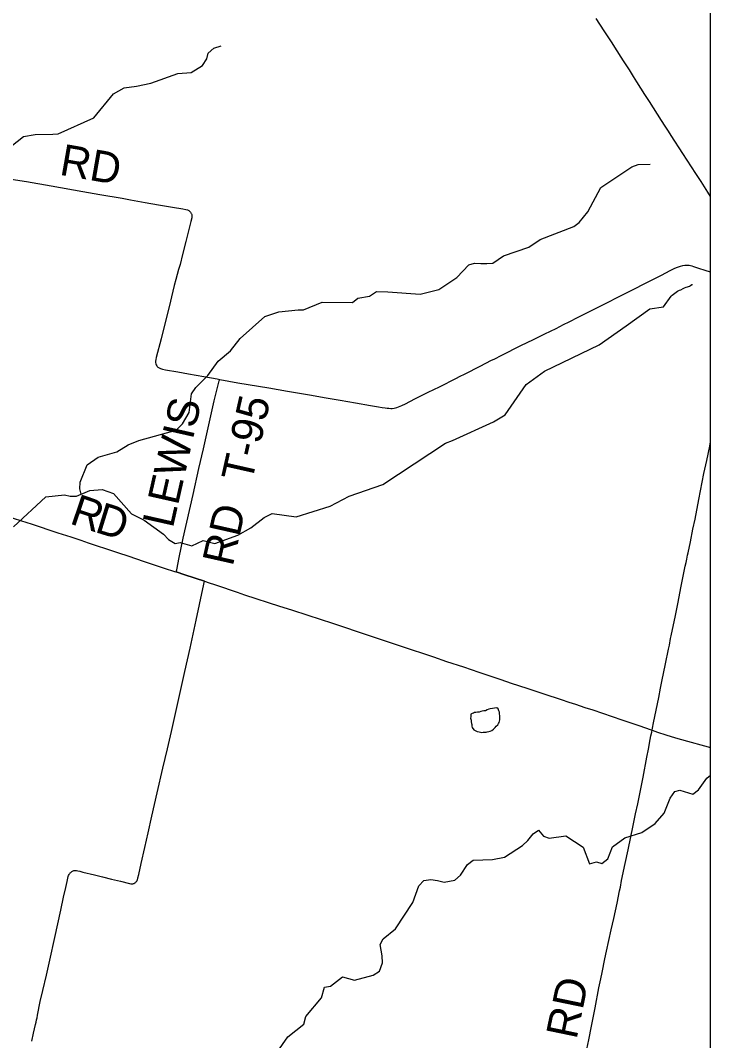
# Model space of a CAD drawing. Extents: x 0 to 34, y 0 to 22.
# Drawn here: x 15.084 to 16.337, y 15.23 to 17.083 of the extents above; entities that cross this region are included whole.
import ezdxf

# ---------------------------------------------------------------- set-up
doc = ezdxf.new("R2010")
doc.units = 0
for name, color, linetype in [('GM_X_Corporation', 7, 'Continuous'), ('GM_X_County_Road', 7, 'Continuous'), ('GM_X_County_Road_Text', 7, 'Continuous'), ('GM_X_Minor_Lake', 7, 'Continuous'), ('GM_X_Minor_River', 7, 'Continuous'), ('GM_X_Township_Road', 7, 'Continuous'), ('GM_X_Township_Road_Text', 7, 'Continuous'), ('GM_X_US_Route', 7, 'Continuous')]:
    doc.layers.add(name, color=color, linetype=linetype)

msp = doc.modelspace()

# ---------------------------------------------------------------- linework, layer by layer
at = {"layer": 'GM_X_Corporation'}
msp.add_lwpolyline([(16.3375, 14.3932), (16.3375, 21.1059), (9.5375, 21.1059), (9.5375, 15.0426), (9.5452, 15.0418), (9.7185, 15.0258), (10.2502, 14.9799), (10.3112, 14.9746), (10.787, 14.9212), (11.3129, 14.8754), (11.3292, 14.8742), (12.1361, 14.7923), (13.6754, 14.6095), (14.714, 14.5341), (15.778, 14.4476), (16.0263, 14.4243)], close=True, dxfattribs=at)
msp.add_lwpolyline([(16.3375, 14.3932), (16.3375, 19.0397)], dxfattribs=at)
at = {"layer": 'GM_X_County_Road'}
for p, q in [((15.3661, 16.0815), (15.3671, 16.0812)), ((15.4185, 16.0643), (15.4221, 16.0631))]:
    msp.add_line(p, q, dxfattribs=at)
for points in [[(15.0613, 16.1823), (15.0958, 16.171), (15.1036, 16.1685), (15.1519, 16.1526), (15.1755, 16.1449), (15.1939, 16.1389), (15.2071, 16.1344), (15.2201, 16.13), (15.242, 16.1229), (15.2624, 16.1161), (15.2793, 16.1103), (15.3091, 16.1005), (15.3451, 16.0884), (15.364, 16.0822), (15.3661, 16.0815)], [(15.3671, 16.0812), (15.3829, 16.076), (15.4185, 16.0643)], [(15.4221, 16.0631), (15.423, 16.0628), (15.44, 16.0571), (15.4778, 16.0445), (15.4913, 16.04), (15.5545, 16.0194), (15.5764, 16.0125), (15.6059, 16.0027), (15.6507, 15.988), (15.7173, 15.9658), (15.7609, 15.9512), (15.788, 15.9422), (15.8217, 15.931), (15.834, 15.9268), (15.8582, 15.9188), (15.8888, 15.9086), (15.9165, 15.8992), (15.9565, 15.8858), (15.9754, 15.8795), (16.0037, 15.8701), (16.0349, 15.8597), (16.0662, 15.8495), (16.0803, 15.8448), (16.0921, 15.8409), (16.1092, 15.8351), (16.1234, 15.8305), (16.1763, 15.8125), (16.2069, 15.8022), (16.2293, 15.7943)], [(16.2293, 15.7943), (16.2312, 15.7936), (16.2408, 15.7902), (16.2562, 15.7852), (16.2735, 15.78), (16.2956, 15.7739), (16.3267, 15.7653), (16.3375, 15.7622)]]:
    msp.add_lwpolyline(points, dxfattribs=at)
at = {"layer": 'GM_X_Minor_Lake'}
msp.add_lwpolyline([(15.9494, 15.8342), (15.9372, 15.8328), (15.9346, 15.8317), (15.9319, 15.8305), (15.9288, 15.829), (15.9258, 15.8287), (15.9228, 15.8283), (15.9201, 15.8276), (15.917, 15.8268), (15.914, 15.8265), (15.911, 15.8257), (15.909, 15.8258), (15.9068, 15.825), (15.9045, 15.8243), (15.9022, 15.8228), (15.9022, 15.8205), (15.9018, 15.8182), (15.9014, 15.8156), (15.9025, 15.8117), (15.9025, 15.8087), (15.9032, 15.806), (15.904, 15.8041), (15.9039, 15.8011), (15.9047, 15.7988), (15.9073, 15.7946), (15.9111, 15.7927), (15.9138, 15.7911), (15.9172, 15.7907), (15.9198, 15.79), (15.9221, 15.7896), (15.9244, 15.7899), (15.9274, 15.7903), (15.9297, 15.7903), (15.932, 15.791), (15.9347, 15.7914), (15.9373, 15.7921), (15.94, 15.7932), (15.9434, 15.7955), (15.9465, 15.7989), (15.9484, 15.8008), (15.9511, 15.8038), (15.9523, 15.8057), (15.9534, 15.808), (15.9542, 15.8099), (15.9546, 15.8125), (15.955, 15.8152), (15.955, 15.8171), (15.955, 15.8205), (15.9543, 15.8228), (15.9539, 15.8266), (15.9532, 15.8289), (15.9521, 15.8308), (15.9517, 15.8327), (15.9494, 15.8342)], dxfattribs=at)
at = {"layer": 'GM_X_Minor_River'}
for points in [[(15.0581, 16.8475), (15.0897, 16.8722), (15.1107, 16.8763), (15.1429, 16.8767), (15.1528, 16.8772), (15.2172, 16.9061), (15.253, 16.9497), (15.2726, 16.961), (15.2951, 16.9639), (15.321, 16.9694), (15.3703, 16.9869), (15.3943, 16.9886), (15.4146, 17.0014), (15.4229, 17.0137), (15.425, 17.0236), (15.4354, 17.0328), (15.4484, 17.0371)], [(15.1947, 16.2227), (15.1918, 16.2324), (15.1924, 16.2445), (15.2056, 16.2758), (15.2252, 16.2897), (15.2592, 16.2996), (15.2796, 16.3124), (15.2991, 16.3203), (15.3671, 16.3388), (15.3787, 16.3507), (15.3905, 16.3713), (15.3947, 16.4047), (15.4025, 16.4167), (15.4242, 16.4382), (15.443, 16.464), (15.4654, 16.4832), (15.483, 16.5056), (15.5278, 16.5455), (15.5534, 16.5541), (15.5884, 16.5578), (15.5983, 16.5576), (15.632, 16.5716), (15.687, 16.5711), (15.6966, 16.5788), (15.7183, 16.5821), (15.7307, 16.591), (15.7512, 16.5905), (15.8099, 16.5857), (15.8442, 16.5944), (15.8769, 16.6164), (15.8987, 16.6391), (15.909, 16.6422), (15.92, 16.6416), (15.931, 16.6417), (15.942, 16.6422), (15.9616, 16.6555), (16.0075, 16.6715), (16.0279, 16.6851), (16.0891, 16.7087), (16.0988, 16.7161), (16.1144, 16.7358), (16.1384, 16.7801), (16.1946, 16.8172), (16.2061, 16.8214), (16.2278, 16.8225)], [(16.2518, 16.5631), (16.2658, 16.5824), (16.2677, 16.5843), (16.27, 16.5861), (16.2723, 16.588), (16.275, 16.5898), (16.2773, 16.5913), (16.2808, 16.5932), (16.2835, 16.5939), (16.2877, 16.5961), (16.2903, 16.5975), (16.2934, 16.5986), (16.2953, 16.5994), (16.2972, 16.6001), (16.2991, 16.6008), (16.3011, 16.6019), (16.3037, 16.6034), (16.3045, 16.6034), (16.3049, 16.6034)], [(15.2099, 16.2293), (15.2323, 16.2311), (15.2534, 16.2237), (15.2857, 16.1869), (15.3086, 16.1753), (15.3437, 16.1502), (15.353, 16.1401), (15.3649, 16.133), (15.3745, 16.1347), (15.3956, 16.1285), (15.4159, 16.1386), (15.437, 16.1328), (15.4787, 16.1482), (15.5025, 16.1617), (15.5265, 16.1801), (15.5414, 16.1874), (15.5849, 16.1814), (15.6464, 16.2009), (15.681, 16.2187), (15.7421, 16.2404), (15.8561, 16.3153), (15.8691, 16.3199), (15.9434, 16.3539), (15.9642, 16.3667), (16.0025, 16.4216), (16.0357, 16.4463), (16.135, 16.4941), (16.1839, 16.5287), (16.2271, 16.5592), (16.2518, 16.5631)], [(15.0715, 16.1634), (15.1304, 16.2175), (15.1642, 16.2216), (15.1744, 16.2191), (15.1858, 16.2189), (15.2099, 16.2293)], [(16.2371, 15.624), (16.2533, 15.6432), (16.2639, 15.6704), (16.2724, 15.6821), (16.2819, 15.685), (16.3053, 15.6778), (16.3157, 15.6853), (16.3307, 15.7067), (16.3375, 15.7118)], [(15.545, 15.2009), (15.5697, 15.2364), (15.5986, 15.2597), (15.6027, 15.2737), (15.6311, 15.3072), (15.6365, 15.3269), (15.6472, 15.3289), (15.6688, 15.3459), (15.6906, 15.3393), (15.7246, 15.3484), (15.7362, 15.3561), (15.7414, 15.3708), (15.7409, 15.3837), (15.7372, 15.4043), (15.7431, 15.4148), (15.7655, 15.4329), (15.7965, 15.4808), (15.8078, 15.5109), (15.8167, 15.5206), (15.8293, 15.5226), (15.8417, 15.5208), (15.8538, 15.5178), (15.8732, 15.5212), (15.8833, 15.5301), (15.8959, 15.5495), (15.9063, 15.5577), (15.9412, 15.5591), (15.9633, 15.5632), (15.996, 15.5841), (16.0057, 15.5933), (16.0154, 15.6056), (16.0251, 15.6119), (16.0339, 15.601), (16.0445, 15.5977), (16.0746, 15.602), (16.106, 15.5811), (16.1179, 15.5512), (16.1301, 15.5543), (16.1399, 15.5514), (16.1511, 15.5603), (16.1591, 15.5818), (16.1815, 15.598), (16.2124, 15.6079), (16.2371, 15.624)]]:
    msp.add_lwpolyline(points, dxfattribs=at)
at = {"layer": 'GM_X_Township_Road'}
for points in [[(15.0671, 16.7952), (15.0951, 16.7905), (15.14, 16.7827), (15.1974, 16.7727), (15.2286, 16.7673), (15.2687, 16.7602), (15.2841, 16.7573), (15.3104, 16.7527), (15.3351, 16.7484), (15.3604, 16.744), (15.3788, 16.741), (15.3843, 16.74), (15.3873, 16.7393), (15.3888, 16.7386), (15.3901, 16.7379), (15.3912, 16.7371), (15.392, 16.7363), (15.3932, 16.735), (15.3939, 16.7338), (15.3945, 16.7328), (15.395, 16.7317), (15.3953, 16.7306), (15.3955, 16.7293), (15.3957, 16.7277), (15.3956, 16.726), (15.3954, 16.7244), (15.3939, 16.7183), (15.3901, 16.7033), (15.3846, 16.6814), (15.3787, 16.6581), (15.374, 16.6401), (15.3715, 16.6311), (15.3664, 16.6126), (15.3634, 16.6018), (15.3609, 16.5916), (15.3541, 16.5628), (15.3466, 16.5322), (15.3396, 16.5046), (15.3309, 16.4711), (15.3301, 16.4674), (15.3297, 16.4643), (15.3297, 16.4619), (15.3301, 16.4595), (15.3307, 16.4577), (15.3318, 16.4555), (15.3326, 16.4545), (15.3339, 16.4532), (15.336, 16.4519), (15.3383, 16.4509), (15.342, 16.4498), (15.3474, 16.4487), (15.3702, 16.4448), (15.3896, 16.4412), (15.4174, 16.4363), (15.4416, 16.432), (15.446, 16.4312)], [(15.446, 16.4312), (15.4787, 16.4252), (15.5351, 16.4157), (15.5693, 16.4099), (15.6091, 16.403), (15.6391, 16.3979), (15.6651, 16.3934), (15.6929, 16.3885), (15.7198, 16.3836), (15.7272, 16.3823), (15.7343, 16.381), (15.7413, 16.38), (15.7468, 16.3792), (15.75, 16.3789), (15.753, 16.3786), (15.7566, 16.3782), (15.7592, 16.3782), (15.7626, 16.3786), (15.765, 16.3793), (15.7679, 16.3802), (15.7707, 16.3812), (15.7766, 16.3835), (15.7836, 16.3867), (15.8006, 16.3958), (15.8246, 16.4077), (15.8452, 16.4178), (15.8763, 16.4334), (15.8818, 16.4362), (15.8918, 16.4412), (15.9189, 16.4552), (15.9397, 16.466), (15.9442, 16.4682), (15.9581, 16.4751), (15.9932, 16.4925), (16.0161, 16.5036), (16.0367, 16.514), (16.0568, 16.5237), (16.0706, 16.5307), (16.0806, 16.5358), (16.0972, 16.5442), (16.1332, 16.5625), (16.186, 16.589), (16.2304, 16.6113), (16.2486, 16.6208), (16.264, 16.6289), (16.2724, 16.633), (16.2775, 16.6353), (16.2828, 16.6371), (16.287, 16.6382), (16.2908, 16.6387), (16.2944, 16.6389), (16.2964, 16.6389), (16.2983, 16.6385), (16.3013, 16.6378), (16.3037, 16.6372), (16.3065, 16.6364), (16.3121, 16.6346), (16.3308, 16.6285), (16.3375, 16.6263)], [(15.3671, 16.0812), (15.3679, 16.0852), (15.3722, 16.1078), (15.3794, 16.1427), (15.3977, 16.2223), (15.4084, 16.2692), (15.4166, 16.3051), (15.4252, 16.3431), (15.4361, 16.3921), (15.4453, 16.4286), (15.446, 16.4312)], [(16.2312, 15.7936), (16.2319, 15.7974), (16.2341, 15.8071), (16.2362, 15.8187), (16.2433, 15.8532), (16.2467, 15.87), (16.2492, 15.8822), (16.2556, 15.9143), (16.2612, 15.9409), (16.2626, 15.9482), (16.265, 15.9601), (16.2661, 15.9655), (16.2737, 16.0022), (16.2784, 16.0261), (16.2837, 16.0523), (16.2916, 16.0916), (16.293, 16.0986), (16.2943, 16.1046), (16.295, 16.1079), (16.2957, 16.1117), (16.2967, 16.1161), (16.3008, 16.136), (16.3055, 16.159), (16.3093, 16.1774), (16.3163, 16.2131), (16.3255, 16.2602), (16.3304, 16.2838), (16.3359, 16.3101), (16.3375, 16.3176)], [(15.4185, 16.0643), (15.3829, 16.076), (15.3671, 16.0812)], [(15.1047, 15.229), (15.1079, 15.2431), (15.1114, 15.2588), (15.1127, 15.2635), (15.1135, 15.2674), (15.1143, 15.2712), (15.1152, 15.2759), (15.1202, 15.3006), (15.1248, 15.321), (15.1312, 15.3488), (15.1374, 15.3759), (15.1464, 15.4172), (15.1573, 15.4669), (15.1626, 15.4906), (15.1664, 15.508), (15.1688, 15.5188), (15.1711, 15.5278), (15.1717, 15.5298), (15.1726, 15.5316), (15.1731, 15.5326), (15.1736, 15.5335), (15.1745, 15.5345), (15.1754, 15.5353), (15.1766, 15.5364), (15.1777, 15.5372), (15.1787, 15.5378), (15.1797, 15.5383), (15.1814, 15.5388), (15.1831, 15.539), (15.1846, 15.5389), (15.1859, 15.5388), (15.1886, 15.5383), (15.1922, 15.5375), (15.1974, 15.5361), (15.2189, 15.5307), (15.2331, 15.5271), (15.2497, 15.5232), (15.2658, 15.5193), (15.2822, 15.5153), (15.2845, 15.5149), (15.2856, 15.5148), (15.287, 15.5148), (15.2885, 15.5149), (15.2897, 15.5151), (15.2906, 15.5155), (15.2913, 15.5158), (15.2927, 15.5167), (15.2934, 15.5174), (15.2941, 15.5181), (15.2948, 15.5189), (15.2953, 15.5197), (15.2961, 15.5211), (15.2966, 15.5221), (15.2969, 15.5231), (15.2973, 15.5244), (15.2975, 15.5254), (15.2989, 15.5316), (15.3034, 15.5514), (15.31, 15.5809), (15.3159, 15.6073), (15.323, 15.6376), (15.3325, 15.68), (15.3428, 15.7248), (15.351, 15.7599), (15.3582, 15.7914), (15.3657, 15.8241), (15.3829, 15.9005), (15.3921, 15.943), (15.4034, 15.9939), (15.4093, 16.0219), (15.4173, 16.0589), (15.4185, 16.0643)], [(16.1108, 15.2057), (16.1161, 15.2314), (16.1212, 15.2562), (16.1278, 15.2892), (16.1347, 15.3254), (16.1384, 15.3421), (16.1406, 15.3533), (16.1455, 15.3781), (16.1485, 15.3922), (16.157, 15.4312), (16.1615, 15.4518), (16.1676, 15.4793), (16.1723, 15.5018), (16.1736, 15.5084), (16.176, 15.5206), (16.1826, 15.5518), (16.1878, 15.5761), (16.1968, 15.6205), (16.2013, 15.6419), (16.2051, 15.6598), (16.2149, 15.7082), (16.2219, 15.7445), (16.2248, 15.7596), (16.2253, 15.7626), (16.2268, 15.7705), (16.2292, 15.7833), (16.2305, 15.7903), (16.2312, 15.7936)]]:
    msp.add_lwpolyline(points, dxfattribs=at)
at = {"layer": 'GM_X_US_Route'}
msp.add_lwpolyline([(16.3375, 16.7637), (16.3326, 16.7712), (16.3201, 16.7905), (16.3106, 16.8051), (16.287, 16.8416), (16.2662, 16.8741), (16.2609, 16.8824), (16.2552, 16.8913), (16.2484, 16.9018), (16.2263, 16.9363), (16.2183, 16.9489), (16.2036, 16.9719), (16.1976, 16.9814), (16.19, 16.9935), (16.1793, 17.0102), (16.1636, 17.0348), (16.1586, 17.0427), (16.1444, 17.0646), (16.1299, 17.0871)], dxfattribs=at)

# ---------------------------------------------------------------- texts
at = {"layer": 'GM_X_County_Road_Text'}
for s, rotation, p in [('R', 341.2263, (15.1716, 16.1699)), ('D', 342.7381, (15.2173, 16.1544))]:
    msp.add_text(s, height=0.0568, rotation=rotation, dxfattribs=at).set_placement(p)
at = {"layer": 'GM_X_Township_Road_Text'}
for s, rotation, p in [('RD', 350.0473, (15.1533, 16.8033)), ('LEWIS', 77.2758, (15.3608, 16.1594)), ('T-95', 77.3043, (15.5041, 16.2419)), ('RD', 77.3043, (15.4695, 16.0899)), ('RD', 78.3088, (16.0939, 15.2305))]:
    msp.add_text(s, height=0.05682, rotation=rotation, dxfattribs=at).set_placement(p)

doc.saveas('drawing.dxf')
